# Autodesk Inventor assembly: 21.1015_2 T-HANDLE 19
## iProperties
Created: 2007-03
Part Number: 21.1015_2 T-HANDLE 19
Document SubType Name: Assembly
Designer: Andy Moles
Mass: 183.899 g
Surface Area: 234.354 cm^2
Volume: 25.7571 cm^3
Density: 7.13977 g/cm^3
Translation Standard: STEP AP214IS
File Name: 1000-U405_ASM
Preprocessor: PRO/ENGINEER BY PARAMETRIC TECHNOLOGY CORPORATION, 2003200
Postprocessor: Build: 344b, Release: 11 SP2 - Date: Fri 08/18/2006
Sent Units: MILLIMETERS
Uncertainty: 0.01136958734563
Author: Andy Moles
